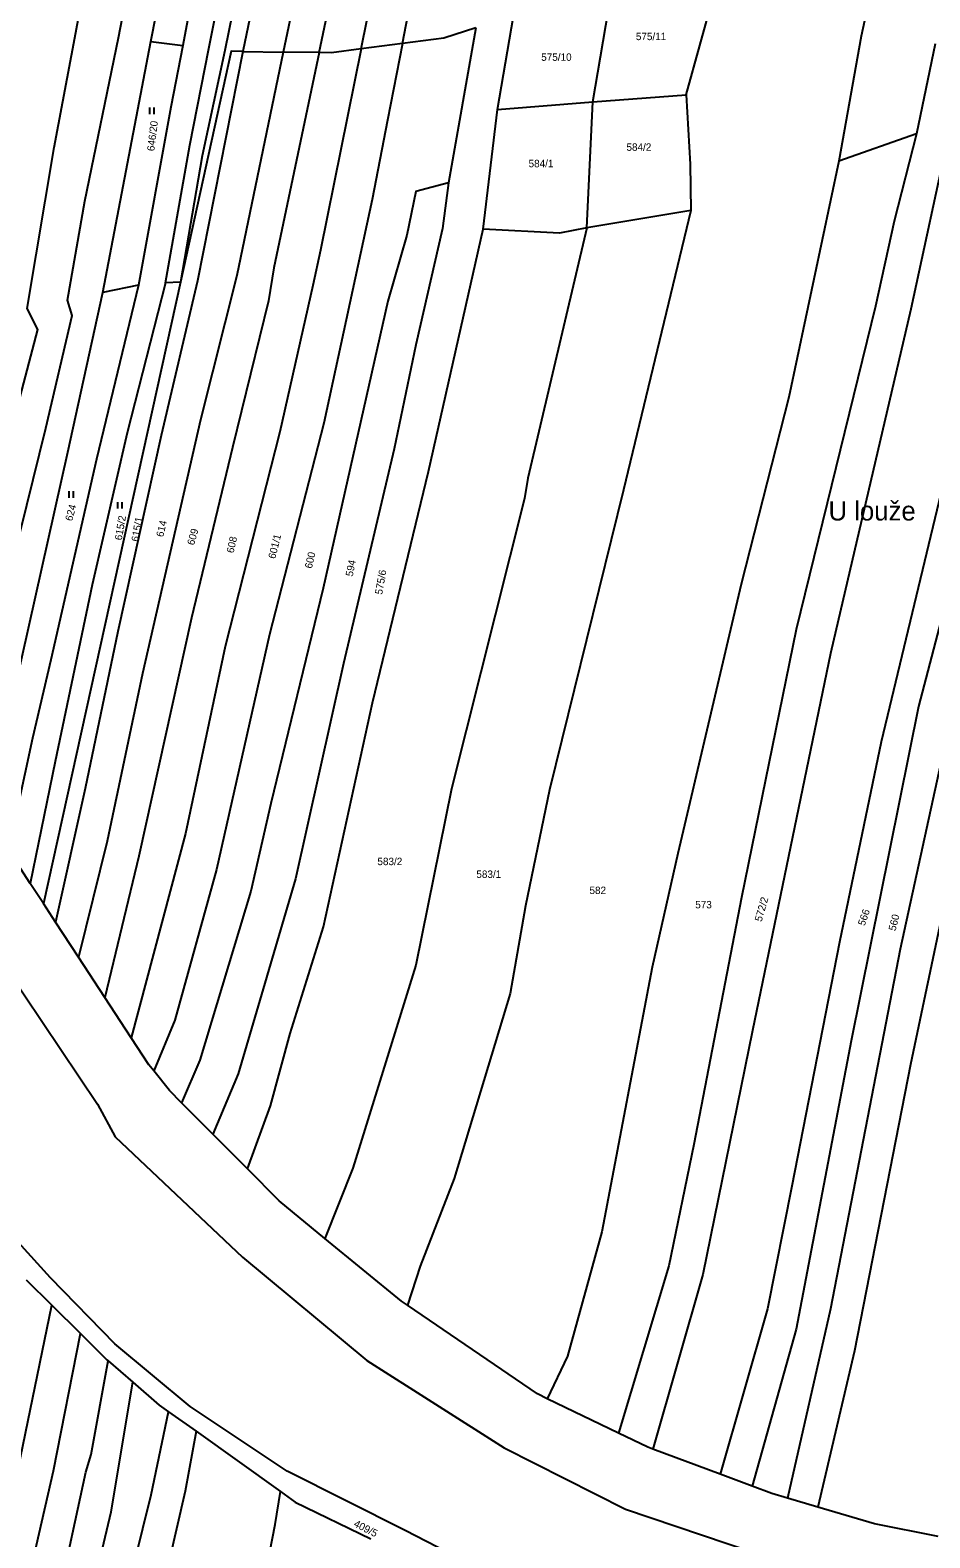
# Model space of a CAD drawing. Extents: x -776734 to -748832, y -1118122 to -976986.
# Drawn here: x -753480.9 to -753275.1, y -1113955.7 to -1113610.9 of the extents above; entities that cross this region are included whole.
import ezdxf

# ---------------------------------------------------------------- set-up
doc = ezdxf.new("R2010")
doc.units = 0
for name, color, linetype in [('KM_Hranice parcel', 7, 'Continuous'), ('KM_Parcelní čísla', 7, 'Continuous'), ('KM_Pop  PČ popisy', 7, 'Continuous'), ('KM_Značky kultur', 7, 'Continuous')]:
    doc.layers.add(name, color=color, linetype=linetype)

msp = doc.modelspace()

# ---------------------------------------------------------------- linework, layer by layer
at = {"layer": 'KM_Hranice parcel'}
for p, q in [((-753352.23, -1113627.25), (-753347.25, -1113598.36)), ((-753330.86, -1113625.62), (-753322.8, -1113596.39)), ((-753373.99, -1113629.03), (-753370.37, -1113607.65)), ((-753378.95, -1113610.36), (-753385.25, -1113645.8)), ((-753464.27, -1113670.84), (-753453.29, -1113613.47)), ((-753453.29, -1113613.47), (-753445.96, -1113614.35)), ((-753432.22, -1113615.73), (-753423.01, -1113615.87)), ((-753414.83, -1113615.99), (-753423.01, -1113615.87)), ((-753395.75, -1113613.91), (-753405.16, -1113615.14)), ((-753273.91, -1113613.95), (-753278.17, -1113634.57)), ((-753352.23, -1113627.25), (-753330.86, -1113625.62)), ((-753377.31, -1113656.39), (-753373.99, -1113629.03)), ((-753373.99, -1113629.03), (-753352.23, -1113627.25)), ((-753353.58, -1113656.08), (-753352.23, -1113627.25)), ((-753278.17, -1113634.57), (-753295.95, -1113640.82)), ((-753329.8, -1113652.08), (-753353.58, -1113656.08)), ((-753446.53, -1113668.47), (-753477.85, -1113810.62)), ((-753456.1, -1113669.16), (-753464.27, -1113670.84)), ((-753446.53, -1113668.47), (-753449.97, -1113668.67)), ((-753480.87, -1113805.99), (-753485.87, -1113798.32)), ((-753477.85, -1113810.62), (-753480.87, -1113805.99)), ((-753475.06, -1113814.88), (-753477.85, -1113810.62)), ((-753469.84, -1113822.86), (-753475.06, -1113814.88)), ((-753463.79, -1113832.11), (-753469.84, -1113822.86)), ((-753457.78, -1113841.3), (-753463.79, -1113832.11)), ((-753439.08, -1113863.39), (-753446.27, -1113856.17)), ((-753431.21, -1113871.3), (-753439.08, -1113863.39)), ((-753481.82, -1113896.66), (-753475.94, -1113902.48)), ((-753475.94, -1113902.48), (-753469.41, -1113908.95)), ((-753463.04, -1113915.23), (-753457.43, -1113920.08)), ((-753449.22, -1113926.84), (-753442.96, -1113931.31)), ((-753346.34, -1113931.73), (-753362.63, -1113923.87)), ((-753442.96, -1113931.31), (-753423.66, -1113945.09)), ((-753323.08, -1113941.14), (-753338.49, -1113935.39)), ((-753315.76, -1113943.87), (-753323.08, -1113941.14)), ((-753300.77, -1113948.64), (-753307.7, -1113946.59))]:
    msp.add_line(p, q, dxfattribs=at)
for points in [[(-753379.21, -1113377.55), (-753388.89, -1113412.31), (-753399.81, -1113462.19), (-753405.91, -1113489.96), (-753411.49, -1113516), (-753419.51, -1113554.46), (-753432.22, -1113615.73)], [(-753369.55, -1113378.06), (-753380.72, -1113416.97), (-753395.78, -1113490.14), (-753402.15, -1113516.59), (-753406.72, -1113536.86), (-753417.42, -1113589.01), (-753423.01, -1113615.87)], [(-753396.29, -1113381.11), (-753401.82, -1113405.19), (-753414.46, -1113458.31), (-753428.33, -1113515.44), (-753436.45, -1113563.44), (-753445.96, -1113614.35)], [(-753414.83, -1113615.99), (-753403.58, -1113562.7), (-753394.35, -1113517.11), (-753388.53, -1113490.21), (-753372.9, -1113425.64), (-753368.18, -1113405.3), (-753361.87, -1113380.08)], [(-753405.16, -1113615.14), (-753393.33, -1113556.29), (-753381.26, -1113495.77), (-753362.97, -1113426.37), (-753353.68, -1113379.73)], [(-753395.75, -1113613.91), (-753389.38, -1113581.06), (-753378.21, -1113525.82), (-753364.88, -1113465.57), (-753355.11, -1113426.95), (-753346.66, -1113379)], [(-753453.29, -1113613.47), (-753449.61, -1113594.86), (-753440.32, -1113545.04), (-753431.67, -1113495.79), (-753428.53, -1113483.8), (-753416.8, -1113438.79), (-753413.34, -1113421.28), (-753404.49, -1113382.76)], [(-753502.88, -1113771.27), (-753494.9, -1113739.14), (-753479.17, -1113679.31), (-753481.55, -1113674.49), (-753475.44, -1113637.71), (-753470.43, -1113611.4), (-753462.26, -1113567.02), (-753454.18, -1113523.38), (-753450.39, -1113499.01)], [(-753496.72, -1113781.33), (-753487.53, -1113743.31), (-753477.31, -1113701.87), (-753471.32, -1113676.12), (-753472.32, -1113672.61), (-753468.39, -1113649.95), (-753460.66, -1113612.58), (-753452.03, -1113567.63), (-753443.46, -1113515.43), (-753442.23, -1113501.01)], [(-753449.97, -1113668.67), (-753444.36, -1113637.15), (-753440.03, -1113615.07), (-753434.19, -1113585.77), (-753431.4, -1113571.08), (-753418.94, -1113515.53)], [(-753415.52, -1113515.71), (-753425, -1113559.61), (-753436.39, -1113615.51), (-753441.57, -1113639.59), (-753446.53, -1113668.47)], [(-753277.32, -1113555.35), (-753279.66, -1113560.55), (-753290.85, -1113612.2), (-753295.95, -1113640.82)], [(-753378.95, -1113610.36), (-753386.3, -1113612.68), (-753395.75, -1113613.91)], [(-753233.28, -1113611.68), (-753237.65, -1113632.2), (-753244.26, -1113663.86), (-753258.3, -1113720.02), (-753272.64, -1113778.46), (-753281.88, -1113821.08), (-753297.81, -1113903.32), (-753307.7, -1113946.59)], [(-753432.22, -1113615.73), (-753442.65, -1113668.19), (-753450.95, -1113703.57), (-753460.87, -1113748.37), (-753468.29, -1113784.28), (-753475.06, -1113814.88)], [(-753423.01, -1113615.87), (-753433.65, -1113666.98), (-753441.97, -1113699.96), (-753455.18, -1113757.96), (-753463.28, -1113796.38), (-753469.84, -1113822.86)], [(-753414.83, -1113615.99), (-753425.17, -1113665.25), (-753426.35, -1113672.74), (-753434.61, -1113706.32), (-753443.96, -1113745.29), (-753456.06, -1113799.74), (-753463.79, -1113832.11)], [(-753405.16, -1113615.14), (-753414.48, -1113661.2), (-753416.22, -1113669.29), (-753423.8, -1113702.75), (-753436.26, -1113751.81), (-753445.35, -1113794.61), (-753457.78, -1113841.3)], [(-753445.96, -1113614.35), (-753448.74, -1113628.5), (-753456.1, -1113669.16)], [(-753395.75, -1113613.91), (-753399.16, -1113631.47), (-753402.65, -1113649.58), (-753413.7, -1113700.74), (-753426.16, -1113749.07), (-753438.29, -1113802.81), (-753447.84, -1113837.31), (-753452.62, -1113848.9)], [(-753432.22, -1113615.73), (-753434.9, -1113615.69), (-753446.53, -1113668.47)], [(-753405.16, -1113615.14), (-753411.97, -1113616.03), (-753414.83, -1113615.99)], [(-753266.33, -1113613.55), (-753270.72, -1113634.09), (-753279.47, -1113674.68), (-753297.87, -1113753.43), (-753315.65, -1113839.66), (-753327.04, -1113895.48), (-753338.49, -1113935.39)], [(-753228.74, -1113622.82), (-753230.65, -1113631.76), (-753237.99, -1113668.06), (-753250.18, -1113719.35), (-753260.25, -1113757.4), (-753271.69, -1113810.11), (-753279.54, -1113847.42), (-753292.39, -1113912.89), (-753300.77, -1113948.64)], [(-753330.86, -1113625.62), (-753329.91, -1113641.47), (-753329.8, -1113652.08)], [(-753253.92, -1113633.68), (-753259.01, -1113659.92), (-753260.71, -1113669.85), (-753262.89, -1113678.29), (-753270.71, -1113708.92), (-753286.27, -1113773.59), (-753295.79, -1113819.46), (-753306.68, -1113875.28), (-753312.29, -1113903.33), (-753323.08, -1113941.14)], [(-753278.17, -1113634.57), (-753283.27, -1113654.54), (-753287.55, -1113673.99), (-753305.71, -1113747.94), (-753318.19, -1113809.22), (-753329.1, -1113865.74), (-753334.79, -1113893.45), (-753346.34, -1113931.73)], [(-753246.71, -1113633.95), (-753251.35, -1113658.7), (-753264.48, -1113714.84), (-753277.69, -1113765.56), (-753293.13, -1113842.04), (-753305.67, -1113907.95), (-753315.76, -1113943.87)], [(-753295.95, -1113640.82), (-753307.41, -1113694.81), (-753318.25, -1113737.58), (-753332.76, -1113799.16), (-753338.62, -1113825.14), (-753350.16, -1113885.69), (-753357.98, -1113914.16), (-753362.63, -1113923.87)], [(-753385.25, -1113645.8), (-753392.7, -1113647.77), (-753394.72, -1113657.73), (-753399.08, -1113672.84), (-753413.87, -1113738.46), (-753425.87, -1113787.72), (-753430.42, -1113807.8), (-753442.11, -1113846.41), (-753446.27, -1113856.17)], [(-753385.25, -1113645.8), (-753386.57, -1113656.23), (-753392.67, -1113682.85), (-753397.62, -1113706.63), (-753409.2, -1113755.71), (-753420.17, -1113804.98), (-753433.35, -1113849.54), (-753439.08, -1113863.39)], [(-753329.8, -1113652.08), (-753345.16, -1113716.02), (-753362.1, -1113784.62), (-753367.64, -1113811.17), (-753371.14, -1113831.22), (-753383.95, -1113873.5), (-753391.66, -1113893.57), (-753394.56, -1113902.5)], [(-753431.21, -1113871.3), (-753425.92, -1113856.91), (-753421.41, -1113840.37), (-753413.81, -1113815.97), (-753402.58, -1113764.68), (-753389.77, -1113711.81), (-753377.31, -1113656.39)], [(-753353.58, -1113656.08), (-753367.06, -1113713.34), (-753367.81, -1113717.98), (-753384.55, -1113784.38), (-753392.68, -1113824.74), (-753407.08, -1113871.17), (-753413.48, -1113887.18)], [(-753353.58, -1113656.08), (-753359.82, -1113657.29), (-753377.31, -1113656.39)], [(-753490.77, -1113790.79), (-753484.17, -1113760.56), (-753472.31, -1113707.34), (-753464.27, -1113670.84)], [(-753456.1, -1113669.16), (-753465.74, -1113708.97), (-753476.15, -1113754.88), (-753480.37, -1113772.76), (-753485.87, -1113798.32)], [(-753449.97, -1113668.67), (-753458.7, -1113702.93), (-753466.69, -1113737.69), (-753475.16, -1113778.1), (-753480.87, -1113805.99)], [(-753137.57, -1114062.53), (-753169.2, -1114046.17), (-753238.04, -1114012.77), (-753255.76, -1114013.39), (-753327.1, -1113989.09), (-753395.12, -1113953.97), (-753422.12, -1113940.41), (-753444.27, -1113925.65), (-753461.53, -1113911.33), (-753476.21, -1113896.23), (-753499.17, -1113870.98), (-753563.91, -1113800.17), (-753574.77, -1113793.36)], [(-753500.22, -1113804.23), (-753490.69, -1113818.96), (-753465.49, -1113856.51), (-753461.43, -1113863.99), (-753432.3, -1113891.5), (-753403.88, -1113915.09), (-753372.45, -1113935.11), (-753344.72, -1113949.13), (-753315.62, -1113958.93), (-753289.76, -1113967.58), (-753256.14, -1113974.52), (-753251.57, -1113974.55)], [(-753452.62, -1113848.9), (-753453.72, -1113847.51), (-753457.78, -1113841.3)], [(-753446.27, -1113856.17), (-753449.03, -1113853.4), (-753452.62, -1113848.9)], [(-753413.48, -1113887.18), (-753423.93, -1113878.62), (-753431.21, -1113871.3)], [(-753394.56, -1113902.5), (-753395.95, -1113901.55), (-753413.48, -1113887.18)], [(-753564.61, -1114325.57), (-753550.12, -1114259.77), (-753537.29, -1114197.74), (-753523.27, -1114130.7), (-753511.38, -1114071.77), (-753496.6, -1113995.29), (-753484.67, -1113945.08), (-753475.94, -1113902.48)], [(-753362.63, -1113923.87), (-753364.89, -1113922.78), (-753394.56, -1113902.5)], [(-753555.9, -1114321.04), (-753550.73, -1114297.2), (-753539.65, -1114242.69), (-753532.15, -1114210.21), (-753521.99, -1114162.01), (-753520.84, -1114158.91), (-753510.57, -1114103.46), (-753502.17, -1114062.33), (-753490.56, -1114005.66), (-753475.57, -1113940.32), (-753469.41, -1113908.95)], [(-753469.41, -1113908.95), (-753463.32, -1113914.98), (-753463.04, -1113915.23)], [(-753547.91, -1114316.89), (-753539.44, -1114272.7), (-753520.11, -1114184.76), (-753509.22, -1114134.56), (-753498.77, -1114084.71), (-753488.88, -1114036.03), (-753482.9, -1114007.57), (-753474.46, -1113969.97), (-753468.16, -1113940.63), (-753466.95, -1113936.62), (-753463.04, -1113915.23)], [(-753538.85, -1114312.17), (-753531.54, -1114274.58), (-753498.78, -1114122.91), (-753484.27, -1114048.85), (-753472.42, -1113992.3), (-753462.34, -1113949.76), (-753457.43, -1113920.08)], [(-753457.43, -1113920.08), (-753451.35, -1113925.32), (-753449.22, -1113926.84)], [(-753530.86, -1114308.02), (-753527.38, -1114288.45), (-753514, -1114225.73), (-753501.6, -1114172.6), (-753490.07, -1114116.74), (-753479.62, -1114062.9), (-753470.71, -1114019.91), (-753462.85, -1113984.68), (-753453.22, -1113945.81), (-753449.22, -1113926.84)], [(-753442.96, -1113931.31), (-753445.42, -1113945.03), (-753450.94, -1113968.89), (-753464.78, -1114027.69), (-753475.54, -1114084.33), (-753487.65, -1114142.57), (-753494.88, -1114175.9), (-753509.56, -1114243.44), (-753521.82, -1114303.32)], [(-753338.49, -1113935.39), (-753339.6, -1113934.98), (-753346.34, -1113931.73)], [(-753307.7, -1113946.59), (-753311.3, -1113945.53), (-753315.76, -1113943.87)], [(-753495.84, -1114289.8), (-753486.79, -1114246.9), (-753475.23, -1114191.81), (-753464.4, -1114139.74), (-753451.98, -1114079.21), (-753441.77, -1114030.67), (-753429.61, -1113976.89), (-753424.88, -1113952.63), (-753423.66, -1113945.09)], [(-753423.66, -1113945.09), (-753420.25, -1113947.52), (-753402.98, -1113955.94)], [(-753273.25, -1113955.38), (-753287.78, -1113952.48), (-753300.77, -1113948.64)]]:
    msp.add_lwpolyline(points, dxfattribs=at)
at = {"layer": 'KM_Značky kultur'}
for p, q in [((-753453.521, -1113630.08), (-753453.521, -1113628.58)), ((-753452.52, -1113630.08), (-753452.52, -1113628.58)), ((-753472.001, -1113717.83), (-753472.001, -1113716.33)), ((-753471, -1113717.83), (-753471, -1113716.33)), ((-753460.831, -1113720.28), (-753460.831, -1113718.78)), ((-753459.83, -1113720.28), (-753459.83, -1113718.78))]:
    msp.add_line(p, q, dxfattribs=at)

# ---------------------------------------------------------------- texts
at = {"layer": 'KM_Parcelní čísla'}
for s, p in [('575/11', (-753342.36, -1113613.14)), ('575/10', (-753364.01, -1113617.87)), ('584/2', (-753344.51, -1113638.45)), ('584/1', (-753366.9, -1113642.21)), ('583/2', (-753401.47, -1113801.83)), ('583/1', (-753378.84, -1113804.75)), ('582', (-753352.97, -1113808.44)), ('573', (-753328.78, -1113811.71))]:
    msp.add_text(s, height=1.7, dxfattribs=at).set_placement(p)
for s, rotation, p in [('646/20', 83, (-753452.506, -1113638.603)), ('624', 75, (-753471.288, -1113723.259)), ('615/2', 80, (-753459.942, -1113727.627)), ('615/1', 80, (-753456.112, -1113727.937)), ('614', 77, (-753450.461, -1113726.901)), ('609', 74, (-753443.422, -1113728.784)), ('608', 77, (-753434.381, -1113730.581)), ('601/1', 76, (-753424.845, -1113731.885)), ('600', 77, (-753416.471, -1113734.111)), ('594', 79, (-753407.125, -1113735.912)), ('575/6', 80, (-753400.382, -1113740.037)), ('572/2', 74, (-753313.602, -1113814.874)), ('566', 71, (-753290.036, -1113815.836)), ('560', 76, (-753282.975, -1113816.985)), ('409/5', 333, (-753407.045, -1113952.997))]:
    msp.add_text(s, height=1.7, rotation=rotation, dxfattribs=at).set_placement(p)
at = {"layer": 'KM_Pop  PČ popisy'}
msp.add_text('U louže', height=4.4, dxfattribs=at).set_placement((-753298.31, -1113723))

doc.saveas('drawing.dxf')
